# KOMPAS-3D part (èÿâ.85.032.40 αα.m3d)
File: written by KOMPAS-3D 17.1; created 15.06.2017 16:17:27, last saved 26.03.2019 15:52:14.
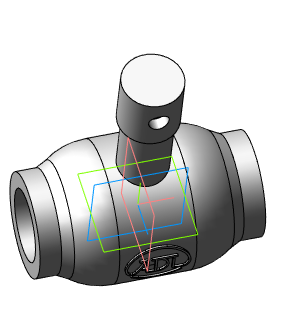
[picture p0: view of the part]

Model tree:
1. Операция без истории:2  (labels: Сталь 20  ГОСТ 1050-88)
